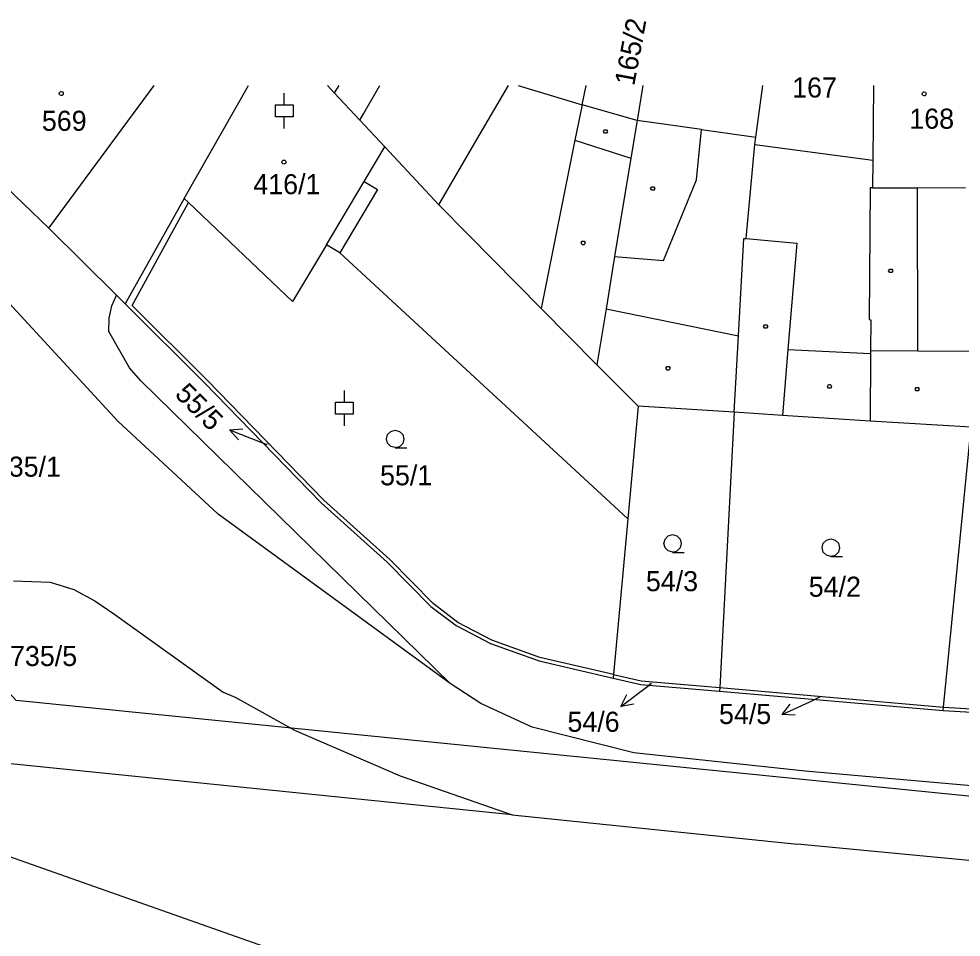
# Model space of a CAD drawing. Extents: x -777309 to -774195, y -1144706 to -1143600.
# Drawn here: x -774968.8 to -774889, y -1144272.1 to -1144194.3 of the extents above; entities that cross this region are included whole.
import ezdxf

# ---------------------------------------------------------------- set-up
doc = ezdxf.new("R2010")
doc.units = 0
for name, color, linetype in [('1', 7, 'Continuous'), ('11', 7, 'Continuous'), ('12', 7, 'Continuous'), ('2', 7, 'Continuous'), ('3', 7, 'Continuous'), ('4', 7, 'Continuous'), ('5', 7, 'Continuous'), ('7', 7, 'Continuous')]:
    doc.layers.add(name, color=color, linetype=linetype)

msp = doc.modelspace()

# ---------------------------------------------------------------- linework, layer by layer
at = {"layer": '1'}
for p, q in [((-774966.27, -1144212.08), (-774957.349, -1144200)), ((-774954.79, -1144209.57), (-774949.343, -1144200)), ((-774942.658, -1144200), (-774942.08, -1144200.62)), ((-774942.08, -1144200.62), (-774939.93, -1144202.92)), ((-774929.99, -1144204.58), (-774927.313, -1144200)), ((-774921.08, -1144201.63), (-774920.748, -1144200)), ((-774915.922, -1144200), (-774916.41, -1144202.95)), ((-774906.36, -1144204.36), (-774905.749, -1144200)), ((-774896.39, -1144200), (-774896.45, -1144206.32)), ((-774921.08, -1144201.63), (-774921.69, -1144204.62)), ((-774939.93, -1144202.92), (-774937.79, -1144205.2)), ((-774916.41, -1144202.95), (-774916.94, -1144206.15)), ((-774933.22, -1144210.1), (-774929.99, -1144204.58)), ((-774921.69, -1144204.62), (-774916.94, -1144206.15)), ((-774906.45, -1144204.98), (-774906.36, -1144204.36)), ((-774973.87, -1144204.8), (-774966.27, -1144212.08)), ((-774937.79, -1144205.2), (-774933.22, -1144210.1)), ((-774907.18, -1144212.96), (-774906.45, -1144204.98)), ((-774916.94, -1144206.15), (-774918.32, -1144214.48)), ((-774896.45, -1144206.32), (-774896.47, -1144208.65)), ((-774896.67, -1144208.65), (-774896.75, -1144219.8)), ((-774896.47, -1144208.65), (-774896.67, -1144208.65)), ((-774954.79, -1144209.57), (-774959.79, -1144218.49)), ((-774954.79, -1144209.57), (-774954.43, -1144209.91)), ((-774959.22, -1144218.63), (-774954.43, -1144209.91)), ((-774954.43, -1144209.91), (-774945.61, -1144218.28)), ((-774933.22, -1144210.1), (-774930.7, -1144212.64)), ((-774960.43, -1144228.43), (-774975.25, -1144212.34)), ((-774966.27, -1144212.08), (-774960.53, -1144217.76)), ((-774930.7, -1144212.64), (-774924.54, -1144218.89)), ((-774942.74, -1144213.49), (-774945.61, -1144218.28)), ((-774941.62, -1144214.16), (-774942.74, -1144213.49)), ((-774907.83, -1144221.21), (-774907.38, -1144212.94)), ((-774907.38, -1144212.94), (-774907.18, -1144212.96)), ((-774917.2, -1144236.71), (-774941.62, -1144214.16)), ((-774918.32, -1144214.48), (-774919.05, -1144218.9)), ((-774960.94, -1144218.67), (-774960.53, -1144217.76)), ((-774960.53, -1144217.76), (-774959.79, -1144218.49)), ((-774961.16, -1144219.71), (-774960.94, -1144218.67)), ((-774959.79, -1144218.49), (-774953.1, -1144225.14)), ((-774952.89, -1144224.93), (-774959.22, -1144218.63)), ((-774924.54, -1144218.89), (-774919.84, -1144223.65)), ((-774919.05, -1144218.9), (-774919.84, -1144223.65)), ((-774961.18, -1144220.83), (-774961.16, -1144219.71)), ((-774896.75, -1144219.8), (-774896.61, -1144219.83)), ((-774896.61, -1144219.83), (-774896.63, -1144222.45)), ((-774959.43, -1144223.9), (-774961.18, -1144220.83)), ((-774908.18, -1144227.67), (-774907.83, -1144221.21)), ((-774896.63, -1144222.69), (-774896.67, -1144228.43)), ((-774896.63, -1144222.45), (-774896.63, -1144222.69)), ((-774958.49, -1144225), (-774959.43, -1144223.9)), ((-774919.84, -1144223.65), (-774916.32, -1144227.15)), ((-774932.25, -1144250.65), (-774958.49, -1144225)), ((-774953.1, -1144225.14), (-774943.18, -1144235.35)), ((-774942.98, -1144235.13), (-774952.89, -1144224.93)), ((-774916.32, -1144227.15), (-774917.2, -1144236.71)), ((-774908.18, -1144227.67), (-774916.32, -1144227.15)), ((-774908.18, -1144227.67), (-774909.41, -1144251)), ((-774904.1, -1144227.94), (-774908.18, -1144227.67)), ((-774896.67, -1144228.43), (-774904.1, -1144227.94)), ((-774951.91, -1144236.31), (-774960.43, -1144228.43)), ((-774888.1, -1144228.93), (-774896.67, -1144228.43)), ((-774890.45, -1144252.65), (-774888.1, -1144228.93)), ((-774937.38, -1144240.15), (-774942.98, -1144235.13)), ((-774943.18, -1144235.35), (-774937.6, -1144240.36)), ((-774932.25, -1144250.65), (-774951.91, -1144236.31)), ((-774917.2, -1144236.71), (-774918.42, -1144249.89)), ((-774937.6, -1144240.36), (-774933.89, -1144244.12)), ((-774933.71, -1144243.88), (-774937.38, -1144240.15)), ((-774969.28, -1144241.95), (-774966.15, -1144242.07)), ((-774966.15, -1144242.07), (-774964.16, -1144242.68)), ((-774964.16, -1144242.68), (-774962.37, -1144243.65)), ((-774962.37, -1144243.65), (-774960.69, -1144244.81)), ((-774931.6, -1144245.47), (-774933.71, -1144243.88)), ((-774933.89, -1144244.12), (-774931.74, -1144245.74)), ((-774960.69, -1144244.81), (-774951.49, -1144251.37)), ((-774928.74, -1144246.97), (-774931.6, -1144245.47)), ((-774931.74, -1144245.74), (-774928.84, -1144247.25)), ((-774924.67, -1144248.45), (-774928.74, -1144246.97)), ((-774928.84, -1144247.25), (-774924.73, -1144248.74)), ((-774918.42, -1144249.89), (-774924.67, -1144248.45)), ((-774924.73, -1144248.74), (-774918.45, -1144250.19)), ((-774918.42, -1144249.89), (-774918.45, -1144250.19)), ((-774918.45, -1144250.19), (-774916.1, -1144250.72)), ((-774929.65, -1144252.35), (-774932.25, -1144250.65)), ((-774916.1, -1144250.72), (-774909.43, -1144251.3)), ((-774909.41, -1144251), (-774909.43, -1144251.3)), ((-774909.41, -1144251), (-774890.45, -1144252.65)), ((-774951.49, -1144251.37), (-774950.48, -1144251.81)), ((-774950.48, -1144251.81), (-774945.44, -1144254.6)), ((-774909.43, -1144251.3), (-774890.48, -1144252.95)), ((-774925.31, -1144254.34), (-774929.65, -1144252.35)), ((-774890.48, -1144252.95), (-774890.45, -1144252.65)), ((-774890.45, -1144252.65), (-774870.47, -1144253.78)), ((-774890.48, -1144252.95), (-774870.51, -1144254.08)), ((-774945.44, -1144254.6), (-774936.5, -1144258.47)), ((-774916.7, -1144256.51), (-774925.31, -1144254.34)), ((-774927.02, -1144261.78), (-774976.9, -1144256.69)), ((-774902.17, -1144258.08), (-774916.7, -1144256.51)), ((-774864.19, -1144261.41), (-774902.17, -1144258.08)), ((-774936.5, -1144258.47), (-774927.02, -1144261.78)), ((-774927.02, -1144261.78), (-774902.82, -1144264.25)), ((-774945.56, -1144273.8), (-774973.93, -1144263.79)), ((-774864.87, -1144267.9), (-774902.82, -1144264.25))]:
    msp.add_line(p, q, dxfattribs=at)
msp.add_lwpolyline([(-774918.42, -1144249.89), (-774916.08, -1144250.42), (-774909.41, -1144251)], dxfattribs=at)
at = {"layer": '11'}
msp.add_lwpolyline([(-774645.079, -1144200), (-774645.5, -1144200.5), (-774681.5, -1144228), (-774709.5, -1144242), (-774744.5, -1144253.5), (-774812, -1144265), (-774860.5, -1144263), (-774969.04, -1144252.1), (-774980.31, -1144239.8), (-774996.3, -1144228.96), (-775000, -1144226.45), (-775000, -1144224.76), (-775020.31, -1144224.68)], dxfattribs=at)
at = {"layer": '12'}
for p, q in [((-774966.27, -1144212.08), (-774957.349, -1144200)), ((-774954.79, -1144209.57), (-774949.343, -1144200)), ((-774942.658, -1144200), (-774942.08, -1144200.62)), ((-774942.658, -1144200), (-774942.08, -1144200.62)), ((-774941.693, -1144200), (-774942.08, -1144200.62)), ((-774942.08, -1144200.62), (-774939.93, -1144202.92)), ((-774926.493, -1144200), (-774921.08, -1144201.63)), ((-774921.08, -1144201.63), (-774920.748, -1144200)), ((-774921.08, -1144201.63), (-774920.748, -1144200)), ((-774915.922, -1144200), (-774916.41, -1144202.95)), ((-774915.922, -1144200), (-774916.41, -1144202.95)), ((-774906.36, -1144204.36), (-774905.749, -1144200)), ((-774906.36, -1144204.36), (-774905.749, -1144200)), ((-774896.39, -1144200), (-774896.45, -1144206.32)), ((-774896.39, -1144200), (-774896.45, -1144206.32)), ((-774916.41, -1144202.95), (-774921.08, -1144201.63)), ((-774939.93, -1144202.92), (-774937.79, -1144205.2)), ((-774910.95, -1144203.72), (-774916.41, -1144202.95)), ((-774910.95, -1144203.72), (-774906.36, -1144204.36)), ((-774906.45, -1144204.98), (-774906.36, -1144204.36)), ((-774973.87, -1144204.8), (-774966.27, -1144212.08)), ((-774939.54, -1144208.13), (-774937.79, -1144205.2)), ((-774906.45, -1144204.98), (-774896.45, -1144206.32)), ((-774896.45, -1144206.32), (-774896.47, -1144208.65)), ((-774942.74, -1144213.49), (-774939.54, -1144208.13)), ((-774896.47, -1144208.65), (-774892.65, -1144208.65)), ((-774892.65, -1144208.65), (-774888.59, -1144208.64)), ((-774954.79, -1144209.57), (-774954.43, -1144209.91)), ((-774954.43, -1144209.91), (-774945.61, -1144218.28)), ((-774942.74, -1144213.49), (-774945.61, -1144218.28)), ((-774945.56, -1144273.8), (-774973.93, -1144263.79))]:
    msp.add_line(p, q, dxfattribs=at)
at = {"layer": '3'}
for p, q in [((-774946.32, -1144201.64), (-774946.32, -1144200.64)), ((-774941.22, -1144226.83), (-774941.22, -1144225.83))]:
    msp.add_line(p, q, dxfattribs=at)
for points in [[(-774946.32, -1144203.64), (-774946.32, -1144202.64), (-774947.07, -1144202.64), (-774947.07, -1144201.64), (-774946.32, -1144201.64), (-774945.57, -1144201.64), (-774945.57, -1144202.64), (-774946.32, -1144202.64)], [(-774941.22, -1144228.83), (-774941.22, -1144227.83), (-774941.97, -1144227.83), (-774941.97, -1144226.83), (-774941.22, -1144226.83), (-774940.47, -1144226.83), (-774940.47, -1144227.83), (-774941.22, -1144227.83)], [(-774936.91, -1144230.67), (-774937.29, -1144230.57), (-774937.56, -1144230.3), (-774937.66, -1144229.93), (-774937.56, -1144229.56), (-774937.29, -1144229.29), (-774936.92, -1144229.19), (-774936.55, -1144229.29), (-774936.28, -1144229.56), (-774936.18, -1144229.94), (-774936.28, -1144230.32), (-774936.55, -1144230.59), (-774936.93, -1144230.69), (-774935.93, -1144230.69)], [(-774913.4, -1144239.52), (-774913.78, -1144239.42), (-774914.05, -1144239.15), (-774914.15, -1144238.78), (-774914.05, -1144238.41), (-774913.78, -1144238.14), (-774913.41, -1144238.04), (-774913.04, -1144238.14), (-774912.77, -1144238.41), (-774912.67, -1144238.79), (-774912.77, -1144239.17), (-774913.04, -1144239.44), (-774913.42, -1144239.54), (-774912.42, -1144239.54)], [(-774899.99, -1144239.88), (-774900.37, -1144239.78), (-774900.64, -1144239.51), (-774900.74, -1144239.14), (-774900.64, -1144238.77), (-774900.37, -1144238.5), (-774900, -1144238.4), (-774899.63, -1144238.5), (-774899.36, -1144238.77), (-774899.26, -1144239.15), (-774899.36, -1144239.53), (-774899.63, -1144239.8), (-774900.01, -1144239.9), (-774899.01, -1144239.9)]]:
    msp.add_lwpolyline(points, dxfattribs=at)
at = {"layer": '4'}
for p, q in [((-774941.693, -1144200), (-774942.08, -1144200.62)), ((-774939.61, -1144202.38), (-774938.211, -1144200)), ((-774926.493, -1144200), (-774921.08, -1144201.63)), ((-774939.93, -1144202.92), (-774939.61, -1144202.38)), ((-774916.41, -1144202.95), (-774921.08, -1144201.63)), ((-774910.95, -1144203.72), (-774916.41, -1144202.95)), ((-774911.38, -1144207.99), (-774910.95, -1144203.72)), ((-774910.95, -1144203.72), (-774906.36, -1144204.36)), ((-774921.69, -1144204.62), (-774924.54, -1144218.89)), ((-774939.54, -1144208.13), (-774937.79, -1144205.2)), ((-774906.45, -1144204.98), (-774896.45, -1144206.32)), ((-774942.74, -1144213.49), (-774939.54, -1144208.13)), ((-774939.54, -1144208.13), (-774938.42, -1144208.8)), ((-774914.18, -1144214.82), (-774911.38, -1144207.99)), ((-774896.47, -1144208.65), (-774892.65, -1144208.65)), ((-774892.65, -1144208.65), (-774888.59, -1144208.64)), ((-774892.63, -1144222.47), (-774892.65, -1144208.65)), ((-774938.42, -1144208.8), (-774941.62, -1144214.16)), ((-774907.18, -1144212.96), (-774902.87, -1144213.36)), ((-774902.87, -1144213.36), (-774903.63, -1144222.36)), ((-774918.32, -1144214.48), (-774914.18, -1144214.82)), ((-774919.05, -1144218.9), (-774907.83, -1144221.21)), ((-774903.63, -1144222.36), (-774904.1, -1144227.94)), ((-774903.63, -1144222.36), (-774896.63, -1144222.69)), ((-774896.63, -1144222.45), (-774892.63, -1144222.47)), ((-774892.63, -1144222.47), (-774888.26, -1144222.49))]:
    msp.add_line(p, q, dxfattribs=at)
at = {"layer": '5'}
for points in [[(-774965.22, -1144200.5), (-774965.12, -1144200.52), (-774965.07, -1144200.61), (-774965.05, -1144200.67), (-774965.07, -1144200.76), (-774965.15, -1144200.83), (-774965.22, -1144200.84), (-774965.31, -1144200.81), (-774965.37, -1144200.75), (-774965.39, -1144200.67), (-774965.37, -1144200.58), (-774965.29, -1144200.51)], [(-774892.09, -1144200.53), (-774891.99, -1144200.55), (-774891.94, -1144200.64), (-774891.92, -1144200.7), (-774891.94, -1144200.79), (-774892.02, -1144200.86), (-774892.09, -1144200.87), (-774892.18, -1144200.84), (-774892.24, -1144200.78), (-774892.26, -1144200.7), (-774892.24, -1144200.61), (-774892.16, -1144200.54)], [(-774919.01, -1144203.74), (-774918.92, -1144203.89), (-774919.01, -1144204.04), (-774919.19, -1144204.04), (-774919.28, -1144203.89), (-774919.19, -1144203.74)], [(-774946.35, -1144206.31), (-774946.25, -1144206.33), (-774946.2, -1144206.42), (-774946.18, -1144206.48), (-774946.2, -1144206.57), (-774946.28, -1144206.64), (-774946.35, -1144206.65), (-774946.44, -1144206.62), (-774946.5, -1144206.56), (-774946.52, -1144206.48), (-774946.5, -1144206.39), (-774946.42, -1144206.32)], [(-774915, -1144208.57), (-774914.91, -1144208.72), (-774915, -1144208.87), (-774915.18, -1144208.87), (-774915.27, -1144208.72), (-774915.18, -1144208.57)], [(-774920.9, -1144213.18), (-774920.81, -1144213.33), (-774920.9, -1144213.48), (-774921.08, -1144213.48), (-774921.17, -1144213.33), (-774921.08, -1144213.18)], [(-774894.83, -1144215.54), (-774894.74, -1144215.69), (-774894.83, -1144215.84), (-774895.01, -1144215.84), (-774895.1, -1144215.69), (-774895.01, -1144215.54)], [(-774905.44, -1144220.26), (-774905.35, -1144220.41), (-774905.44, -1144220.56), (-774905.62, -1144220.56), (-774905.71, -1144220.41), (-774905.62, -1144220.26)], [(-774913.7, -1144223.8), (-774913.61, -1144223.95), (-774913.7, -1144224.1), (-774913.88, -1144224.1), (-774913.97, -1144223.95), (-774913.88, -1144223.8)], [(-774900.02, -1144225.33), (-774899.93, -1144225.48), (-774900.02, -1144225.63), (-774900.2, -1144225.63), (-774900.29, -1144225.48), (-774900.2, -1144225.33)], [(-774892.59, -1144225.57), (-774892.5, -1144225.72), (-774892.59, -1144225.87), (-774892.77, -1144225.87), (-774892.86, -1144225.72), (-774892.77, -1144225.57)]]:
    msp.add_lwpolyline(points, close=True, dxfattribs=at)
at = {"layer": '7'}
for p, q in [((-774950.948, -1144229.163), (-774948.16, -1144230.27)), ((-774947.77, -1144230.43), (-774948.16, -1144230.27)), ((-774917.792, -1144252.587), (-774915.39, -1144250.79)), ((-774915.24, -1144250.68), (-774915.39, -1144250.79)), ((-774901.03, -1144251.84), (-774901.41, -1144252.02)), ((-774904.129, -1144253.288), (-774901.41, -1144252.02))]:
    msp.add_line(p, q, dxfattribs=at)
for points in [[(-774950.203, -1144229.997), (-774950.948, -1144229.163), (-774949.835, -1144229.068)], [(-774916.692, -1144252.388), (-774917.792, -1144252.587), (-774917.291, -1144251.588)], [(-774903.011, -1144253.318), (-774904.129, -1144253.288), (-774903.434, -1144252.412)]]:
    msp.add_lwpolyline(points, dxfattribs=at)

# ---------------------------------------------------------------- texts
at = {"layer": '2'}
for s, height, rotation, p in [('165/2', 1.7, 79.41195, (-774916.668, -1144200.074)), ('55/5', 0.1, 313.98087, (-774947.888, -1144230.308))]:
    msp.add_text(s, height=height, rotation=rotation, dxfattribs=at).set_placement(p)
for s, height, p in [('167', 1.7, (-774903.277, -1144201.01)), ('569', 1.7, (-774966.863, -1144203.83)), ('168', 1.7, (-774893.347, -1144203.65)), ('416/1', 1.7, (-774948.943, -1144209.2)), ('1735/1', 1.7, (-774972.197, -1144233.13)), ('55/1', 1.7, (-774938.203, -1144233.86)), ('54/3', 1.7, (-774915.673, -1144242.83)), ('54/2', 1.7, (-774901.873, -1144243.3)), ('1735/5', 1.7, (-774970.827, -1144249.17)), ('54/6', 0.1, (-774915.404, -1144250.68)), ('54/5', 0.1, (-774901.057, -1144251.88))]:
    msp.add_text(s, height=height, dxfattribs=at).set_placement(p)
at = {"layer": '7'}
msp.add_text('55/5', height=1.7, rotation=314.9549, dxfattribs=at).set_placement((-774955.678, -1144226.229))
for s, p in [('54/5', (-774909.478, -1144254.08)), ('54/6', (-774922.321, -1144254.74))]:
    msp.add_text(s, height=1.7, dxfattribs=at).set_placement(p)

doc.saveas('drawing.dxf')
